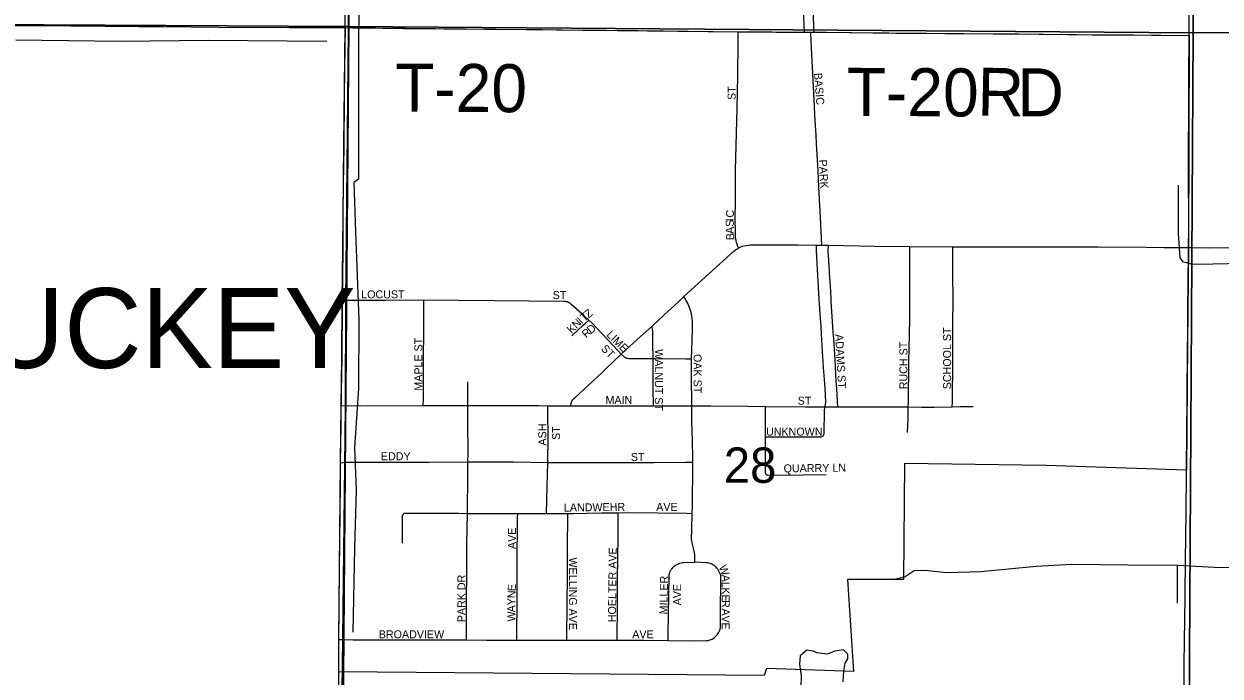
# Model space of a CAD drawing. Extents: x 1443599 to 1910620, y 1028088 to 1361369.
# Drawn here: x 1694297 to 1701772, y 1256858 to 1260936 of the extents above; entities that cross this region are included whole.
import ezdxf

# ---------------------------------------------------------------- set-up
doc = ezdxf.new("R2010")
doc.units = 0
for name, color, linetype in [('GM_X_City_Street', 7, 'Continuous'), ('GM_X_City_Street_Text', 7, 'Continuous'), ('GM_X_Corporation', 7, 'Continuous'), ('GM_X_Corporation_Text', 7, 'Continuous'), ('GM_X_County_Road', 7, 'Continuous'), ('GM_X_Minor_Lake', 7, 'Continuous'), ('GM_X_Minor_River', 7, 'Continuous'), ('GM_X_Section', 7, 'Continuous'), ('GM_X_Section_Text', 7, 'Continuous'), ('GM_X_State_Route', 7, 'Continuous'), ('GM_X_Township', 7, 'Continuous'), ('GM_X_Township_Road', 7, 'Continuous'), ('GM_X_Township_Road_Text', 7, 'Continuous')]:
    doc.layers.add(name, color=color, linetype=linetype)

msp = doc.modelspace()

# ---------------------------------------------------------------- linework, layer by layer
at = {"layer": 'GM_X_City_Street'}
for points in [[(1698762.6, 1259535.2), (1698757.4, 1259549.3), (1698754.1, 1259558.2), (1698750.7, 1259569.3), (1698747.4, 1259582.5), (1698744.6, 1259602.4), (1698743.9, 1259622.3), (1698742.6, 1259730.8), (1698743.7, 1259814.8), (1698744.4, 1260021.4), (1698753.8, 1260407.6), (1698757.7, 1260610.8), (1698760.4, 1260822.7), (1698761.2, 1260885.6)], [(1699174.7, 1260884.5), (1699215.5, 1260883.9)], [(1699282.6, 1259552.8), (1699280.7, 1259593.1), (1699276.5, 1259684.9), (1699264.8, 1259917.3), (1699259.9, 1260018.2), (1699250.9, 1260185.2), (1699247.6, 1260240.8), (1699242.4, 1260332.4), (1699240.5, 1260368.3), (1699237.7, 1260420.6), (1699229.4, 1260581), (1699227, 1260626.8), (1699220.5, 1260744.6), (1699217.5, 1260828.3), (1699215.5, 1260883.9)], [(1699215.5, 1260883.9), (1699232.6, 1260883.8)], [(1699305.3, 1258542.6), (1699308.3, 1258571.7), (1699306, 1258614.8), (1699303.4, 1258656.9), (1699299.9, 1258713.1), (1699294.9, 1258788.4), (1699292.8, 1258824.5), (1699288.5, 1258886.7), (1699286.4, 1258922.7), (1699281.6, 1258998), (1699278.5, 1259047), (1699274.1, 1259119.3), (1699269.8, 1259188.1), (1699267.5, 1259217), (1699264.9, 1259251.6), (1699255.5, 1259399.4), (1699251.6, 1259475.1), (1699250.6, 1259523.4), (1699250.2, 1259552.9)], [(1699383.7, 1258541.5), (1699381.4, 1258577.1), (1699376.4, 1258657), (1699373.5, 1258702.7), (1699371.1, 1258745.1), (1699370.3, 1258764.6), (1699369.9, 1258774.3), (1699369.5, 1258787.2), (1699368.6, 1258800.1), (1699364, 1258872.1), (1699357.8, 1258966.7), (1699354.7, 1259008.7), (1699352.5, 1259041), (1699348.7, 1259106.1), (1699342.8, 1259201.1), (1699341.7, 1259217.1), (1699338.9, 1259262.4), (1699332.8, 1259353.6), (1699331.7, 1259372.5), (1699331, 1259384.8), (1699330.7, 1259390.8), (1699324.8, 1259487.1), (1699323.9, 1259514.6), (1699324, 1259524), (1699324.3, 1259552.5)], [(1699823.6, 1258542.1), (1699824.9, 1258571), (1699827.5, 1258820.4), (1699832.5, 1259088.6), (1699832.7, 1259264.1), (1699834.2, 1259421.5), (1699833.7, 1259509.9), (1699833.3, 1259545.2)], [(1700097, 1258542), (1700099.2, 1258575.4), (1700100.9, 1258618.4), (1700102.1, 1258787.8), (1700101.2, 1259029.2), (1700103.3, 1259244.2), (1700102.9, 1259338.5), (1700102.3, 1259497), (1700102.2, 1259542.7)], [(1698469.9, 1258841.8), (1698471.5, 1258898.1), (1698474.2, 1258957), (1698474.6, 1259032.2), (1698474.7, 1259077), (1698473.4, 1259093.1), (1698471.2, 1259108.3), (1698468.2, 1259123.9), (1698464.7, 1259138.2), (1698459, 1259156), (1698451.2, 1259176.5), (1698441.6, 1259195.5), (1698421.6, 1259230.7)], [(1696285.6, 1259208.2), (1696339.1, 1259208.3), (1696555.8, 1259208.8), (1696797, 1259210.1), (1696797.1, 1259210.1)], [(1696792.8, 1258550.7), (1696793.1, 1258586.7), (1696794.8, 1258790), (1696796.3, 1259069.4), (1696797.1, 1259210.1)], [(1696797.1, 1259210.1), (1697454.2, 1259203.5), (1697675, 1259202.4), (1697679.4, 1259201.9), (1697684.4, 1259201), (1697688.8, 1259199.8), (1697694.6, 1259197.6)], [(1697826.6, 1259084.4), (1697797, 1259112.8), (1697717.8, 1259182.2), (1697710, 1259188.5), (1697704.8, 1259192.2), (1697699.9, 1259195), (1697694.6, 1259197.6)], [(1697720.3, 1258985.3), (1697725.1, 1258989.8), (1697789.3, 1259050.5), (1697803.5, 1259063.3), (1697826.6, 1259084.4)], [(1698029.7, 1258871.1), (1698011.7, 1258891.1), (1697845.4, 1259066.3), (1697826.6, 1259084.4)], [(1698228.5, 1258843.2), (1698228.2, 1258934.3), (1698227.8, 1259004.6), (1698227.1, 1259015), (1698226, 1259022), (1698222.7, 1259045.5)], [(1698029.7, 1258871.1), (1698050.3, 1258852.7), (1698055.6, 1258849.5), (1698062.1, 1258846.9), (1698068.2, 1258845.3), (1698076.4, 1258844.5), (1698086.8, 1258844), (1698228.5, 1258843.2)], [(1698228.5, 1258843.2), (1698243.3, 1258843.1), (1698433, 1258842), (1698469.9, 1258841.8)], [(1698231.5, 1258547.6), (1698230.4, 1258656.8), (1698229.4, 1258754.5), (1698228.9, 1258804.4), (1698228.5, 1258843.2)], [(1698471.2, 1258547.5), (1698471, 1258585), (1698469.2, 1258702.6), (1698469.6, 1258828.6), (1698469.9, 1258841.8)], [(1697070.9, 1258550.4), (1697071.8, 1258697.4)], [(1697072, 1258197.3), (1697072.3, 1258248.9), (1697071.3, 1258451.1), (1697070.9, 1258550.4)], [(1697571.4, 1258194.5), (1697572.3, 1258349.5), (1697572, 1258508.9), (1697571.9, 1258548.8)], [(1697712.4, 1258548.7), (1697918.6, 1258548.5), (1698098.7, 1258547.8), (1698231.5, 1258547.6)], [(1698231.5, 1258547.6), (1698295.2, 1258547.5), (1698396.9, 1258547.2), (1698471.2, 1258547.5)], [(1698471.2, 1258547.5), (1698590.5, 1258548.1), (1698821.7, 1258545.1), (1698931.3, 1258543.8)], [(1698477, 1258195.3), (1698476.4, 1258255.2), (1698475.9, 1258300.4), (1698474.5, 1258341.4), (1698473.4, 1258376.8), (1698471.9, 1258467.7), (1698471.2, 1258547.5)], [(1698931.3, 1258543.8), (1699181.7, 1258540.9), (1699305.3, 1258542.6)], [(1698931.5, 1258354.3), (1698931.4, 1258504), (1698931.3, 1258543.8)], [(1698931.5, 1258354.3), (1698945.8, 1258354.2), (1699061.7, 1258353.4), (1699276.7, 1258353.3), (1699281.9, 1258354.6), (1699286, 1258356.5), (1699289.5, 1258358.7), (1699292.3, 1258361.1), (1699294.7, 1258365), (1699296.5, 1258369.6), (1699297.6, 1258374.1), (1699298.6, 1258383.7), (1699299.7, 1258512.2), (1699300.5, 1258524), (1699305.3, 1258542.6)], [(1699305.3, 1258542.6), (1699383.7, 1258541.5)], [(1699383.7, 1258541.5), (1699467, 1258541.5), (1699643.8, 1258542), (1699823.6, 1258542.1)], [(1699819.7, 1258380.5), (1699821.2, 1258427.3), (1699822.2, 1258469.5), (1699823.6, 1258542.1)], [(1699823.6, 1258542.1), (1699906.3, 1258540.3), (1699985, 1258540.3), (1700097, 1258542)], [(1700097, 1258542), (1700147.8, 1258542.9), (1700229.4, 1258543.9)], [(1698936.3, 1258119.3), (1698934.3, 1258121.2), (1698932.6, 1258124.5), (1698931.7, 1258127.5), (1698931.5, 1258354.3)], [(1696276.2, 1258192.6), (1696308.2, 1258195.5), (1696570.1, 1258196.5), (1696830.2, 1258196.6), (1697072, 1258197.3)], [(1697068.5, 1257875.6), (1697071.9, 1258120.1), (1697072, 1258197.3)], [(1697072, 1258197.3), (1697357.5, 1258197.7), (1697571.4, 1258194.5)], [(1697563.5, 1257875), (1697567, 1258042.9), (1697571.4, 1258194.5)], [(1697571.4, 1258194.5), (1697672.3, 1258193), (1698233.4, 1258194), (1698430.2, 1258195.1), (1698477, 1258195.3)], [(1698473, 1257875.6), (1698474.3, 1257922.2), (1698477.2, 1258177.6), (1698477, 1258195.3)], [(1698936.3, 1258119.3), (1698938.4, 1258117.1), (1698940.6, 1258115.8), (1698943, 1258114.9), (1698945.6, 1258114.7), (1699168.6, 1258117), (1699309.9, 1258118.6)], [(1696668, 1257871.6), (1696670.4, 1257874.2), (1696673.7, 1257876.6), (1696676.9, 1257877.6), (1696680.8, 1257878), (1696891.2, 1257876.7), (1697014.5, 1257876.2), (1697068.5, 1257875.6)], [(1697061.9, 1257084.7), (1697062, 1257148.6), (1697065.5, 1257686.2), (1697068.5, 1257875.6)], [(1697068.5, 1257875.6), (1697136.6, 1257874.4), (1697249, 1257875.7), (1697383.3, 1257875.1)], [(1697376.6, 1257082.6), (1697376.8, 1257108.7), (1697379, 1257331.6), (1697379.9, 1257544.2), (1697382.6, 1257847.1), (1697383.3, 1257875.1)], [(1697383.3, 1257875.1), (1697498, 1257874.7), (1697563.5, 1257875)], [(1697563.5, 1257875), (1697629.3, 1257875.4), (1697696.6, 1257875.7)], [(1697690.2, 1257083.1), (1697690.3, 1257118.9), (1697691.1, 1257284.6), (1697693.2, 1257512), (1697693.6, 1257697.4), (1697695.7, 1257823.8), (1697696.6, 1257875.7)], [(1697696.6, 1257875.7), (1697727.3, 1257875.9), (1697905.8, 1257879), (1698011.7, 1257879.9)], [(1698004.8, 1257082.5), (1698005.2, 1257119.7), (1698006.4, 1257265.6), (1698006.6, 1257460.8), (1698010.2, 1257726), (1698011.4, 1257845.8), (1698011.7, 1257879.9)], [(1698011.7, 1257879.9), (1698073.4, 1257880.4), (1698440, 1257876.2), (1698473, 1257875.6)], [(1698490, 1257570), (1698490, 1257617.3), (1698488.7, 1257630.8), (1698486.5, 1257641.6), (1698474.8, 1257684.2), (1698472.2, 1257694.6), (1698470.4, 1257706.3), (1698469.1, 1257715.9), (1698470.4, 1257777.6), (1698473, 1257875.6)], [(1696663.5, 1257689.3), (1696663, 1257858), (1696663.8, 1257861.9), (1696665.1, 1257865.8), (1696666.2, 1257868.9), (1696668, 1257871.6)], [(1698323.8, 1257081), (1698324.1, 1257117.5), (1698324.9, 1257243.5), (1698328.9, 1257483), (1698329.8, 1257492.8), (1698331.2, 1257500.3), (1698333.5, 1257508.4), (1698337.2, 1257516.6), (1698342.4, 1257524.7), (1698347.6, 1257531.6), (1698355, 1257539.2), (1698361.7, 1257545.7), (1698369.9, 1257552), (1698378.4, 1257557), (1698386.9, 1257561), (1698394.7, 1257563.8), (1698404, 1257566.6), (1698412.3, 1257568.4), (1698423.1, 1257569.4), (1698490, 1257570)], [(1698617.8, 1257104.1), (1698623.9, 1257110.1), (1698629.3, 1257116.4), (1698634.3, 1257123.1), (1698638.2, 1257129.4), (1698642.1, 1257136.8), (1698645.2, 1257145), (1698647.3, 1257152.8), (1698649.5, 1257162.2), (1698650.8, 1257171.7), (1698649.2, 1257244.4), (1698652.8, 1257476.2), (1698652, 1257485.1), (1698650.2, 1257493.3), (1698646.5, 1257502.2), (1698642.4, 1257510.7), (1698638.5, 1257518.3), (1698633.1, 1257527), (1698628.3, 1257533.5), (1698622.2, 1257539.8), (1698615.9, 1257545.6), (1698609.8, 1257550.2), (1698602.9, 1257555), (1698595.7, 1257558.7), (1698588.3, 1257561.9), (1698579.8, 1257564.5), (1698570.7, 1257566.3), (1698562, 1257567.1), (1698490, 1257570)], [(1696265.8, 1257088.1), (1696302.3, 1257087.2), (1696357.7, 1257085.8), (1696619.5, 1257084.9), (1696750.8, 1257084.5), (1697000.1, 1257084.6), (1697061.9, 1257084.7)], [(1697061.9, 1257084.7), (1697187.2, 1257083.3), (1697364.4, 1257082.5), (1697376.6, 1257082.6)], [(1697376.6, 1257082.6), (1697501.7, 1257082.9), (1697637.8, 1257083.3), (1697690.2, 1257083.1)], [(1697690.2, 1257083.1), (1697877.8, 1257082.3), (1698004.8, 1257082.5)], [(1698004.8, 1257082.5), (1698171.5, 1257082.7), (1698323.8, 1257081)], [(1698323.8, 1257081), (1698453.6, 1257079.5), (1698562.9, 1257080.4), (1698574.6, 1257081.7), (1698584.2, 1257084.1), (1698591.3, 1257086.5), (1698598.5, 1257090), (1698605.2, 1257094.2), (1698611.7, 1257098.7), (1698617.8, 1257104.1)]]:
    msp.add_lwpolyline(points, dxfattribs=at)
at = {"layer": 'GM_X_Corporation'}
msp.add_lwpolyline([(1699104.3, 1263574.6), (1699232.6, 1260883.8), (1701579.8, 1260862.8), (1701575, 1259537.7), (1701568.9, 1258942.4), (1701562.3, 1258146), (1700684.9, 1258176), (1699799.4, 1258188.4), (1699794.6, 1257462.9), (1699443.4, 1257461.5), (1699481.8, 1256887.7), (1698936.8, 1256905.6), (1698922.4, 1256862.7), (1696264.5, 1256884.2), (1696265.8, 1257088.1), (1696276.3, 1258195.4), (1696279.7, 1258549.3), (1696284, 1258846.1), (1696285.6, 1259208.2), (1696289.3, 1259532.4), (1696295.8, 1260172.7), (1696304.5, 1260914.2), (1698761.2, 1260885.6), (1699174.6, 1260884.5), (1699056, 1263579.9)], dxfattribs=at)
at = {"layer": 'GM_X_County_Road'}
for points in [[(1696304.5, 1260914.2), (1696304.4, 1261010.6)], [(1696276.2, 1258192.6), (1696279.5, 1258425.8), (1696279.7, 1258549.3)], [(1696265.8, 1257088.1), (1696267.3, 1257277.6), (1696269.4, 1257543.8), (1696270.3, 1257673.8), (1696274.2, 1257906.8), (1696274.9, 1258044.8), (1696276.2, 1258192.6)], [(1696264.5, 1256884.2), (1696264.7, 1256955.8), (1696265.8, 1257088.1)], [(1696257.1, 1255550.6), (1696257.2, 1255562.3), (1696258.1, 1255718.6), (1696259.6, 1255892.1), (1696259.7, 1255977.4), (1696260.5, 1256059.5), (1696260.9, 1256144.8), (1696261.7, 1256256.3), (1696261.1, 1256374.6), (1696262.2, 1256469.6), (1696263.8, 1256548.4), (1696262.4, 1256669.9), (1696264.5, 1256884.2)]]:
    msp.add_lwpolyline(points, dxfattribs=at)
at = {"layer": 'GM_X_Minor_Lake'}
msp.add_line((1699317.3, 1256994.9), (1699251.5, 1257004.5), dxfattribs=at)
for points in [[(1699251.5, 1257004.5), (1699229.8, 1257015), (1699189.9, 1257020), (1699149.1, 1256984.9), (1699143.8, 1256932.9), (1699154, 1256860.6), (1699152.2, 1256788.5)], [(1699417, 1256822.1), (1699420.6, 1256888.2), (1699429.9, 1256940), (1699446.5, 1256965.7), (1699445.3, 1256995.8), (1699418, 1257022.5), (1699365.7, 1257013.7), (1699317.3, 1256994.9)]]:
    msp.add_lwpolyline(points, dxfattribs=at)
at = {"layer": 'GM_X_Minor_River'}
for points in [[(1696404.7, 1262915.5), (1696396.4, 1262413.6), (1696392.3, 1261924.7), (1696392.8, 1261301.5), (1696388, 1260784.6), (1696387.7, 1259965.1), (1696359.2, 1259943.8), (1696369.5, 1259634.9), (1696389.8, 1259085.4), (1696387.2, 1258656.7), (1696362, 1258286.6), (1696373.5, 1258021.8), (1696362.4, 1257657.4), (1696353.4, 1257132.7)], [(1694247, 1260836.8), (1694905.4, 1260828.5), (1695447.4, 1260833.4), (1696189.1, 1260827.5)], [(1701911.4, 1259438.8), (1701727.4, 1259433.2), (1701597.3, 1259432.3), (1701541.3, 1259448.8), (1701522.3, 1259474.2), (1701517.9, 1259536.4), (1701511.8, 1259625.2), (1701511.6, 1259927.3)], [(1701922, 1257533), (1701738.2, 1257537.4), (1701504.5, 1257549.1), (1701196.7, 1257552.5), (1700844.9, 1257557), (1700622.6, 1257544.4), (1700450.2, 1257526.5), (1700277.9, 1257510.6), (1700062.5, 1257504.4), (1699928.2, 1257519.1), (1699860.1, 1257516.7), (1699805.2, 1257480), (1699728.7, 1257459.8), (1699702.8, 1257462.4)], [(1701504.5, 1257549.1), (1701504.7, 1257314.6)]]:
    msp.add_lwpolyline(points, dxfattribs=at)
at = {"layer": 'GM_X_Section'}
for points in [[(1696341.3, 1266293.5), (1696328, 1260918.8), (1690993.2, 1260949.6), (1691034.3, 1266328.1)], [(1701653.9, 1266270.7), (1701604.3, 1260880.3), (1696328, 1260918.8), (1696341.3, 1266293.5)], [(1706926.2, 1266222.3), (1706905.4, 1260905.6), (1701604.3, 1260880.3), (1701653.9, 1266270.7)], [(1696328, 1260918.8), (1696283.1, 1255588.5), (1690974.3, 1255593.1), (1690993.2, 1260949.6)], [(1701604.3, 1260880.3), (1701573.5, 1255563.9), (1696283.1, 1255588.5), (1696328, 1260918.8)], [(1706905.4, 1260905.6), (1706870.2, 1255567.1), (1701573.5, 1255563.9), (1701604.3, 1260880.3)]]:
    msp.add_lwpolyline(points, close=True, dxfattribs=at)
at = {"layer": 'GM_X_State_Route'}
for points in [[(1694218.5, 1260925.2), (1694587.7, 1260923.4), (1695014.3, 1260919.6), (1695170.3, 1260918.8), (1695514.8, 1260916), (1695957.9, 1260913.8), (1696187.7, 1260912.4), (1696304.5, 1260914.2)], [(1696304.5, 1260914.2), (1696302.3, 1260790), (1696300.1, 1260655.4), (1696298.9, 1260471.5), (1696295.8, 1260172.7), (1696292.5, 1259929.7), (1696290.2, 1259745.9), (1696289.3, 1259532.4), (1696287.4, 1259348.5), (1696285.6, 1259223.8), (1696285.6, 1259208.2), (1696285.4, 1259122), (1696283.8, 1258918.5), (1696284, 1258846.1), (1696280.5, 1258642.6), (1696279.7, 1258549.3)], [(1697929.5, 1258776.2), (1698029.7, 1258871.1), (1698130.3, 1258962.2), (1698222.7, 1259045.5), (1698297, 1259114.4), (1698388.5, 1259199.2), (1698421.6, 1259230.7), (1698734.2, 1259514.3), (1698744, 1259522.6), (1698751.6, 1259528.3), (1698759.8, 1259533.7), (1698762.6, 1259535.2), (1698768.5, 1259538.7), (1698777, 1259542.4), (1698787.4, 1259545.8), (1698797.8, 1259548.4), (1698810.6, 1259551.1), (1698823.2, 1259553), (1698835, 1259554.3), (1698848, 1259554.8), (1699136, 1259554.1), (1699250.2, 1259552.9), (1699282.6, 1259552.8), (1699324.3, 1259552.5), (1699612.3, 1259547.3), (1699833.3, 1259545.2), (1700102.2, 1259542.7), (1700424.5, 1259541.8), (1701008.6, 1259541.3), (1701309.6, 1259539.4)], [(1701309.6, 1259539.4), (1701420, 1259538.7)], [(1701420, 1259538.7), (1701575, 1259537.7)], [(1701575, 1259537.7), (1701593.2, 1259537.5), (1701698.1, 1259536.1), (1702366.3, 1259537.6), (1702810.3, 1259542.6), (1703040.1, 1259545.2), (1703230.4, 1259545.3), (1703578, 1259548.6), (1703748.5, 1259550.7), (1703974.6, 1259549.1), (1704168.3, 1259549.7), (1704278, 1259550.2), (1704586.2, 1259550.9), (1704852.1, 1259551.7), (1705147.5, 1259552.4), (1705383.9, 1259553), (1706000.8, 1259552.7), (1706899.5, 1259549.9)], [(1697739.3, 1258598.9), (1697909.7, 1258757.5), (1697929.5, 1258776.2)], [(1696279.7, 1258549.3), (1696441.1, 1258548.9), (1696792.8, 1258550.7), (1696802.2, 1258550.8), (1696883.7, 1258550.7)], [(1696883.7, 1258550.7), (1697070.9, 1258550.4), (1697353.7, 1258549.9), (1697512.2, 1258549.2), (1697513.9, 1258549.2)], [(1697513.9, 1258549.2), (1697571.9, 1258548.8), (1697623.5, 1258548.5), (1697712.4, 1258548.7), (1697718.9, 1258571.1), (1697722.2, 1258579.6), (1697725.4, 1258584.8), (1697729.3, 1258589.6), (1697739.3, 1258598.9)]]:
    msp.add_lwpolyline(points, dxfattribs=at)
at = {"layer": 'GM_X_Township'}
for points in [[(1691028.1, 1266317.4), (1696325.2, 1266275.9), (1696323.7, 1260893.6), (1696307.5, 1259201.1), (1696305.1, 1258547.4), (1696300.6, 1258173.2), (1696287.7, 1257097.2), (1696269.5, 1255586.8), (1696154.1, 1250250)], [(1691028.1, 1266317.4), (1696325.2, 1266275.9), (1696323.7, 1260893.6), (1696307.5, 1259201.1), (1696305.1, 1258547.4), (1696300.6, 1258173.2), (1696287.7, 1257097.2), (1696269.5, 1255586.8), (1696154.1, 1250250), (1695980.1, 1244960.3), (1695885, 1241542.2), (1695846.2, 1239693.5), (1695686.2, 1234411.7), (1693554.1, 1234401)]]:
    msp.add_lwpolyline(points, dxfattribs=at)
at = {"layer": 'GM_X_Township_Road'}
for points in [[(1701579.8, 1260862.8), (1701579.4, 1261153.3), (1701581.4, 1261313.2), (1701582.3, 1261454.3), (1701582.1, 1261634.8), (1701583.4, 1261776), (1701585.1, 1262005.3), (1701586.5, 1262190.7), (1701587.3, 1262496), (1701593.1, 1262886.5), (1701600.2, 1263451.2), (1701602.4, 1263654.8), (1701604.2, 1263776.2), (1701607.9, 1264186.5), (1701611.6, 1264577.1), (1701613.4, 1264757.6), (1701620, 1265098.9), (1701628.2, 1265446.8), (1701630.5, 1265604.3), (1701632.4, 1265735.6), (1701634.8, 1266054), (1701634.3, 1266241.1), (1701634.8, 1266283.9)], [(1696304.5, 1260914.2), (1696353, 1260912.1), (1696390.1, 1260910.9), (1696415.3, 1260910.3), (1696665.7, 1260906.9), (1697177.5, 1260902), (1697535.1, 1260901.2), (1697787.7, 1260897.7), (1697935.4, 1260896.2), (1698138.8, 1260894.5), (1698761.2, 1260885.6)], [(1698761.2, 1260885.6), (1698819.4, 1260885.4), (1698973.6, 1260885.3), (1698996.5, 1260885.2), (1699174.7, 1260884.5)], [(1699232.6, 1260883.8), (1699313.5, 1260884.1), (1699746.6, 1260879), (1700051.8, 1260876.1), (1700356, 1260873.1), (1700513.5, 1260872.9), (1700972.9, 1260868.1), (1701232.2, 1260866.6), (1701579.8, 1260862.8)], [(1701575, 1259537.7), (1701576.6, 1259655), (1701576.5, 1259766.4), (1701575.6, 1259920.6), (1701577.3, 1260599.2), (1701579.8, 1260862.8)], [(1701567.1, 1258659.8), (1701570.2, 1259043.1), (1701571.6, 1259200.4), (1701573, 1259274.8), (1701573.6, 1259363.2), (1701574, 1259461.6), (1701575, 1259537.7)], [(1701566.4, 1258575.3), (1701567, 1258625.6), (1701567.1, 1258659.8)], [(1701532, 1255544.6), (1701533.6, 1255634.4), (1701536, 1255913.4), (1701536.9, 1256057.9), (1701540.6, 1256294.1), (1701542.1, 1256455), (1701545.3, 1256665.1), (1701548.4, 1256936), (1701553.9, 1257352), (1701555.9, 1257603.9), (1701557.6, 1257705.6), (1701561.8, 1258102.8), (1701565.5, 1258431), (1701566, 1258542.7), (1701566.4, 1258575.3)]]:
    msp.add_lwpolyline(points, dxfattribs=at)

# ---------------------------------------------------------------- texts
at = {"layer": 'GM_X_City_Street_Text'}
for s, rotation, p in [('BASIC', 274.28713, (1699234.5, 1260628)), ('ST', 90, (1698744.9, 1260460.1)), ('PARK', 273.01099, (1699265.3, 1260086.6)), ('C', 86.30548, (1698732.5, 1259723.7)), ('S', 91.66406, (1698733.7, 1259667.7)), ('I', 90.30593, (1698732.7, 1259702.6)), ('A', 91.66156, (1698735, 1259623.7)), ('B', 91.67612, (1698736.1, 1259584.2)), ('LOCUST', 0.00001, (1696404.8, 1259219.9)), ('ST', 0.00001, (1697601.5, 1259215.5)), ('Z', 38.22472, (1697825.2, 1259093.7)), ('N', 43.28395, (1697750.4, 1259027.3)), ('I', 41.84418, (1697782.2, 1259057.3)), ('T', 39.21444, (1697798.1, 1259071.5)), ('K', 43.29987, (1697718.4, 1258997.2)), ('R', 41.56294, (1697810.5, 1258969.3)), ('D', 38.05901, (1697839.5, 1258995.1)), ('LIME', 315, (1697933.8, 1258988.3)), ('ADAMS ST', 273.2713, (1699366.5, 1258995.3)), ('SCHOOL ST', 90, (1700091.3, 1258651.7)), ('MAPLE ST', 90, (1696786.9, 1258642.9)), ('ST', 315, (1697899.4, 1258901.1)), ('RUCH ST', 90, (1699818.5, 1258651.7)), ('WALNUT ST', 270, (1698240.2, 1258902.5)), ('OAK ST', 270, (1698482.1, 1258871.7)), ('MAIN', 0.00001, (1697931.5, 1258559.9)), ('ST', 0.00001, (1699132.7, 1258555.5)), ('ASH', 90, (1697561.3, 1258299.7)), ('ST', 90, (1697647.4, 1258334.9)), ('UNKNOWN', 0.00001, (1698934.7, 1258361.9)), ('EDDY', 0.00001, (1696528, 1258207.9)), ('ST', 0.00001, (1698089.9, 1258203.5)), ('QUARRY LN', 0.69671, (1699044.9, 1258131.8)), ('LANDWEHR', 0.71787, (1697671.8, 1257886.7)), ('AVE', 0.00001, (1698248.3, 1257891.1)), ('AVE', 90, (1697372.1, 1257652.9)), ('HOELTER AVE', 89.40439, (1697996.9, 1257195.1)), ('WELLING AVE', 270, (1697703.4, 1257600.1)), ('W', 290.87093, (1698638.2, 1257541)), ('PARK DR', 90, (1697056, 1257195.3)), ('E', 87.51281, (1697370.2, 1257388.2)), ('MILLER', 88.89885, (1698318.2, 1257243.9)), ('AVE', 90, (1698404.2, 1257300.9)), ('A', 270.50279, (1698657.7, 1257492.1)), ('L', 269.83605, (1698658.1, 1257448.3)), ('N', 87.66045, (1697368.4, 1257344.3)), ('E', 269.81892, (1698657.9, 1257369.1)), ('K', 269.82511, (1698658, 1257413.1)), ('Y', 89.19122, (1697367.8, 1257300.7)), ('A', 89.95627, (1697367.7, 1257256.9)), ('A', 269.82372, (1698657.6, 1257281.1)), ('R', 269.82997, (1698657.8, 1257333.9)), ('W', 89.98318, (1697367.7, 1257199.7)), ('V', 269.82511, (1698657.5, 1257237.1)), ('BROADVIEW', 0.00001, (1696514.7, 1257094.7)), ('AVE', 0.00001, (1698098.7, 1257094.7)), ('E', 269.83244, (1698657.3, 1257193.1))]:
    msp.add_text(s, height=50, rotation=rotation, dxfattribs=at).set_placement(p)
at = {"layer": 'GM_X_Corporation_Text'}
msp.add_text('LUCKEY', height=500, rotation=0.00001, dxfattribs=at).set_placement((1693694.4, 1258784.2))
at = {"layer": 'GM_X_Section_Text'}
msp.add_text('28', height=221, rotation=0.00001, dxfattribs=at).set_placement((1698670.7, 1258066.8))
at = {"layer": 'GM_X_Township_Road_Text'}
for s, rotation, p in [('T-20', 359.65156, (1696615.5, 1260388.2)), ('T-20', 359.64565, (1699438.3, 1260361.8)), ('R', 358.84464, (1700253.8, 1260363.2)), ('D', 359.96644, (1700506.5, 1260358.1))]:
    msp.add_text(s, height=300, rotation=rotation, dxfattribs=at).set_placement(p)

doc.saveas('drawing.dxf')
